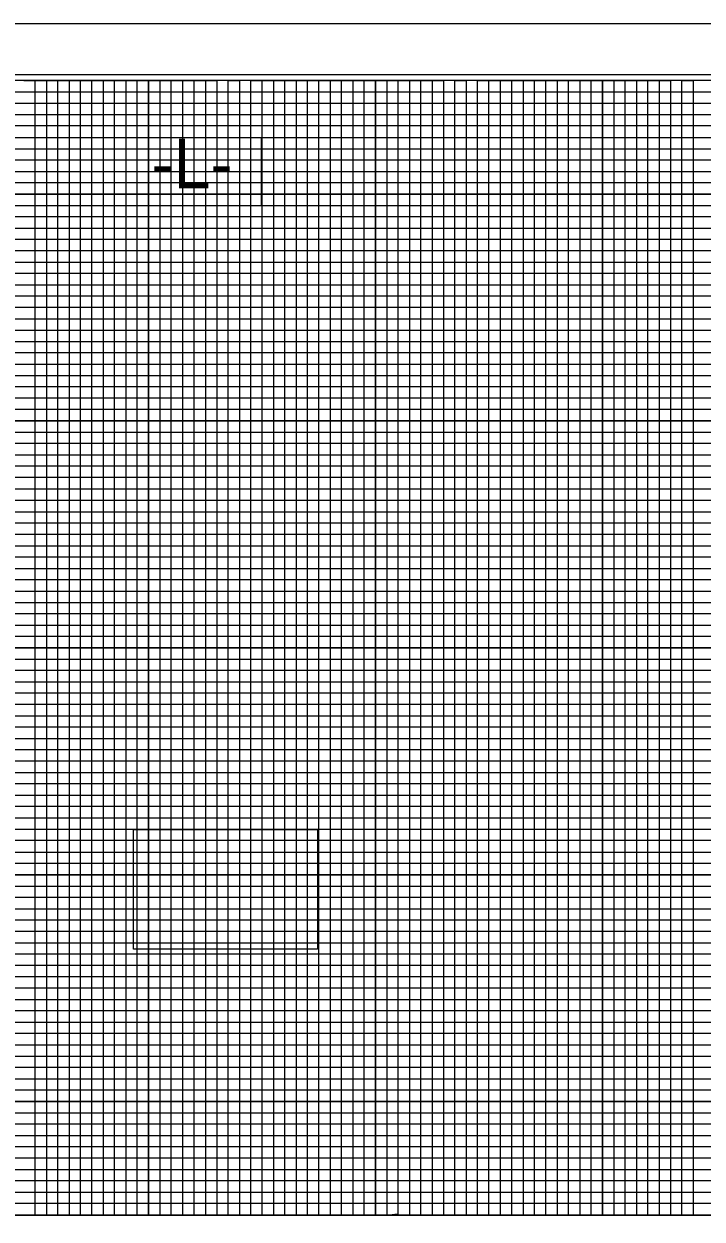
# Model space of a CAD drawing. Extents: x 1623313 to 1628771, y 891211 to 901910.
# Drawn here: x 1624175 to 1624474, y 901333 to 901859 of the extents above; entities that cross this region are included whole.
import ezdxf

# ---------------------------------------------------------------- set-up
doc = ezdxf.new("R2010")
doc.units = 0
for name, color, linetype in [('Prop DSN Text', 7, 'Continuous'), ('Prop PHM Black Shape', 7, 'Continuous'), ('Scratch_Level_0', 7, 'Continuous'), ('Sheet Cutting Line CELL', 7, 'Continuous'), ('Sheet DOT Grid CELL', 7, 'Continuous'), ('Sheet Layout Profile Border Port 1', 7, 'Continuous'), ('Sheet Plot Border Inside CELL', 7, 'Continuous'), ('Sheet Plot Border Outside CELL', 7, 'Continuous'), ('Sheet Profile CELL', 7, 'Continuous'), ('Sheet Profile Grid Major CELL', 7, 'Continuous'), ('Sheet Profile Grid Middle CELL', 7, 'Continuous'), ('Sheet Profile Grid Minor CELL', 7, 'Continuous')]:
    doc.layers.add(name, color=color, linetype=linetype)

msp = doc.modelspace()

# ---------------------------------------------------------------- linework, layer by layer
at = {"layer": 'Prop DSN Text'}
msp.add_lwpolyline([(1624229.95, 901809.45), (1624279.54, 901809.45), (1624279.54, 901779.22), (1624229.95, 901779.22)], close=True, dxfattribs=at)
at = {"layer": 'Prop PHM Black Shape'}
for points in [[(1624229.95, 901809.45), (1624279.54, 901809.45), (1624279.54, 901779.22), (1624229.95, 901779.22)], [(1624223.32, 901504.36), (1624304.32, 901504.36), (1624304.32, 901451.64), (1624223.32, 901451.64)]]:
    msp.add_lwpolyline(points, close=True, dxfattribs=at)
at = {"layer": 'Scratch_Level_0'}
msp.add_lwpolyline([(1623529.95, 901824.45), (1624929.95, 901824.45), (1624929.95, 901334.45), (1623529.95, 901334.45)], close=True, dxfattribs=at)
at = {"layer": 'Sheet Cutting Line CELL'}
msp.add_line((1624996.95, 901859.45), (1623312.95, 901859.45), dxfattribs=at)
at = {"layer": 'Sheet DOT Grid CELL'}
for p, q in [((1624179.95, 901334.45), (1624179.95, 901834.45)), ((1624229.95, 901334.45), (1624229.95, 901834.45)), ((1624279.95, 901334.45), (1624279.95, 901834.45)), ((1624329.95, 901334.45), (1624329.95, 901834.45)), ((1624379.95, 901334.45), (1624379.95, 901834.45)), ((1624429.95, 901334.45), (1624429.95, 901834.45)), ((1624779.9, 901784.45), (1623479.95, 901784.45)), ((1624779.9, 901734.45), (1623479.95, 901734.45)), ((1624779.95, 901684.45), (1623479.95, 901684.45)), ((1624979.95, 901634.45), (1623479.95, 901634.45)), ((1624979.95, 901584.45), (1623479.95, 901584.45)), ((1624979.95, 901534.45), (1623479.95, 901534.45)), ((1624979.95, 901484.45), (1623479.95, 901484.45)), ((1624979.95, 901434.45), (1623479.95, 901434.45)), ((1624979.95, 901384.45), (1623479.95, 901384.45))]:
    msp.add_line(p, q, dxfattribs=at)
at = {"layer": 'Sheet Layout Profile Border Port 1'}
msp.add_lwpolyline([(1623529.95, 901673.4), (1623529.95, 901334.45), (1624929.95, 901334.45), (1624929.95, 901673.4)], dxfattribs=at)
at = {"layer": 'Sheet Plot Border Inside CELL'}
msp.add_lwpolyline([(1623325.95, 900781.9), (1624992.45, 900781.9), (1624992.45, 901837), (1623325.95, 901837)], close=True, dxfattribs=at)
at = {"layer": 'Sheet Plot Border Outside CELL'}
msp.add_lwpolyline([(1623312.95, 900759.45), (1624996.95, 900759.45), (1624996.95, 901859.45), (1623312.95, 901859.45)], close=True, dxfattribs=at)
at = {"layer": 'Sheet Profile CELL'}
msp.add_line((1623479.95, 901334.45), (1624979.95, 901334.45), dxfattribs=at)
msp.add_lwpolyline([(1624979.95, 901834.45), (1623479.95, 901834.45), (1623479.95, 900784.45), (1624979.95, 900784.45)], close=True, dxfattribs=at)
at = {"layer": 'Sheet Profile Grid Major CELL'}
for points in [[(1624129.95, 901334.45), (1624179.95, 901334.45), (1624179.95, 901834.45), (1624229.95, 901834.45), (1624229.95, 901334.45), (1624279.95, 901334.45), (1624279.95, 901834.45), (1624329.95, 901834.45), (1624329.95, 901334.45), (1624379.95, 901334.45), (1624379.95, 901834.45), (1624429.95, 901834.45), (1624429.95, 901334.45), (1624479.95, 901334.45)], [(1623479.95, 901784.45), (1624779.95, 901784.45)], [(1624779.95, 901734.45), (1623479.95, 901734.45), (1623479.95, 901684.45), (1624779.95, 901684.45)], [(1624979.95, 901634.45), (1623479.95, 901634.45), (1623479.95, 901584.45), (1624979.95, 901584.45)], [(1624979.95, 901534.45), (1623479.95, 901534.45), (1623479.95, 901484.45), (1624979.95, 901484.45)], [(1624979.95, 901434.45), (1623479.95, 901434.45), (1623479.95, 901434.45), (1623479.95, 901384.45), (1624979.95, 901384.45)]]:
    msp.add_lwpolyline(points, dxfattribs=at)
at = {"layer": 'Sheet Profile Grid Middle CELL'}
msp.add_line((1623479.95, 901809.45), (1624779.9, 901809.45), dxfattribs=at)
for points in [[(1624154.95, 901334.45), (1624204.95, 901334.45), (1624204.95, 901834.45), (1624254.95, 901834.45), (1624254.95, 901334.45), (1624304.95, 901334.45), (1624304.95, 901834.45), (1624354.95, 901834.45), (1624354.95, 901334.45), (1624404.95, 901334.45), (1624404.95, 901834.45), (1624454.95, 901834.45), (1624454.95, 901334.45), (1624504.95, 901334.45)], [(1624779.95, 901759.45), (1623479.95, 901759.45), (1623479.95, 901709.45), (1624779.95, 901709.45)], [(1624979.95, 901659.45), (1623479.95, 901659.45), (1623479.95, 901609.45), (1624804.95, 901609.45)], [(1624979.95, 901559.45), (1623479.95, 901559.45), (1623479.95, 901509.45), (1624979.95, 901509.45)], [(1624979.95, 901459.45), (1623479.95, 901459.45), (1623479.95, 901409.45), (1624979.95, 901409.45)], [(1624979.95, 901359.45), (1623479.95, 901359.45)]]:
    msp.add_lwpolyline(points, dxfattribs=at)
at = {"layer": 'Sheet Profile Grid Minor CELL'}
for p, q in [((1623529.95, 901829.45), (1624779.95, 901829.45)), ((1624779.95, 901824.45), (1623529.95, 901824.1)), ((1623529.95, 901819.45), (1624779.95, 901819.45)), ((1624779.9, 901699.45), (1623529.95, 901699.45)), ((1624779.95, 901694.45), (1623529.95, 901694.45)), ((1624779.95, 901689.45), (1623529.95, 901689.45)), ((1623529.95, 901679.45), (1624779.95, 901679.45)), ((1624779.95, 901674.45), (1623529.95, 901674.45)), ((1623529.95, 901669.45), (1624929.95, 901669.45)), ((1624929.95, 901649.45), (1623529.95, 901649.45)), ((1623529.95, 901644.45), (1624929.95, 901644.45)), ((1624929.95, 901624.45), (1623529.95, 901624.45)), ((1623529.95, 901619.45), (1624929.95, 901619.45)), ((1624929.95, 901599.45), (1623529.95, 901599.45)), ((1623529.95, 901594.45), (1624929.95, 901594.45)), ((1624929.95, 901589.45), (1623529.95, 901589.45)), ((1623529.95, 901579.45), (1624929.95, 901579.45)), ((1624929.95, 901574.45), (1623529.95, 901574.45)), ((1623529.95, 901569.45), (1624929.95, 901569.45)), ((1624929.95, 901564.45), (1623529.95, 901564.45)), ((1623529.95, 901554.45), (1624929.95, 901554.45)), ((1624929.95, 901549.45), (1623529.95, 901549.45)), ((1623529.95, 901544.45), (1624929.95, 901544.45)), ((1624929.95, 901539.45), (1623529.95, 901539.45)), ((1623529.95, 901529.45), (1624929.95, 901529.45)), ((1624929.95, 901524.45), (1623529.95, 901524.45)), ((1623529.95, 901519.45), (1624929.95, 901519.45)), ((1624929.95, 901514.45), (1623529.95, 901514.45)), ((1623529.95, 901504.45), (1624929.95, 901504.45)), ((1624929.95, 901499.45), (1623529.95, 901499.45)), ((1623529.95, 901494.45), (1624929.95, 901494.45)), ((1624929.95, 901489.45), (1623529.95, 901489.45)), ((1623529.95, 901479.45), (1624929.95, 901479.45)), ((1624929.95, 901474.45), (1623529.95, 901474.45)), ((1623529.95, 901469.45), (1624929.95, 901469.45)), ((1624929.95, 901464.45), (1623529.95, 901464.45)), ((1623529.95, 901454.45), (1624929.95, 901454.45)), ((1624929.95, 901449.45), (1623529.95, 901449.45)), ((1624929.95, 901444.45), (1623529.95, 901444.45)), ((1624929.95, 901439.45), (1623529.95, 901439.45)), ((1623529.95, 901429.45), (1624929.95, 901429.45)), ((1624929.95, 901424.45), (1623529.95, 901424.45)), ((1623529.95, 901419.45), (1624929.95, 901419.45)), ((1624929.95, 901414.45), (1623529.95, 901414.45)), ((1623529.95, 901404.45), (1624929.95, 901404.45)), ((1624929.95, 901399.45), (1623529.95, 901399.45)), ((1623529.95, 901394.45), (1624929.95, 901394.45)), ((1624929.95, 901389.45), (1623529.95, 901389.45)), ((1623529.95, 901379.45), (1624929.95, 901379.45)), ((1624929.95, 901374.45), (1623529.95, 901374.45)), ((1623529.95, 901369.45), (1624929.95, 901369.45)), ((1624929.95, 901364.45), (1623529.95, 901364.45)), ((1623529.95, 901354.45), (1624929.95, 901354.45)), ((1624929.95, 901349.45), (1623529.95, 901349.45)), ((1623529.95, 901344.45), (1624929.95, 901344.45))]:
    msp.add_line(p, q, dxfattribs=at)
for points in [[(1624174.95, 901834.45), (1624184.95, 901834.45), (1624184.95, 901334.45), (1624184.95, 901334.45), (1624189.95, 901334.45), (1624189.95, 901834.45), (1624194.95, 901834.45), (1624194.95, 901334.45), (1624199.95, 901334.45), (1624199.95, 901834.45), (1624209.95, 901834.45), (1624209.95, 901334.45), (1624214.95, 901334.45), (1624214.95, 901834.45), (1624219.95, 901834.45), (1624219.95, 901334.45), (1624224.95, 901334.45), (1624224.95, 901834.45), (1624234.95, 901834.45), (1624234.95, 901334.45), (1624239.95, 901334.45), (1624239.95, 901834.45), (1624244.95, 901834.45), (1624244.95, 901334.45), (1624249.95, 901334.45), (1624249.95, 901834.45), (1624259.95, 901834.45), (1624259.95, 901334.45), (1624264.95, 901334.45), (1624264.95, 901834.45), (1624269.95, 901834.45), (1624269.95, 901334.45), (1624274.95, 901334.45), (1624274.95, 901834.45), (1624284.95, 901834.45), (1624284.95, 901334.45), (1624289.95, 901334.45), (1624289.95, 901834.45), (1624294.95, 901834.45), (1624294.95, 901334.45), (1624299.95, 901334.45), (1624299.95, 901834.45), (1624309.95, 901834.45), (1624309.95, 901334.45), (1624314.95, 901334.45), (1624314.95, 901834.45), (1624319.95, 901834.45), (1624319.95, 901334.45), (1624324.95, 901334.45), (1624324.95, 901834.45), (1624334.95, 901834.45), (1624334.95, 901334.45), (1624339.65, 901335), (1624339.95, 901334.45), (1624339.95, 901834.45), (1624344.95, 901834.45), (1624344.95, 901334.45), (1624349.95, 901334.45), (1624349.95, 901834.45), (1624359.95, 901834.45), (1624359.95, 901334.45), (1624364.95, 901334.45)], [(1624364.95, 901334.45), (1624364.95, 901834.45), (1624369.95, 901834.45), (1624369.95, 901334.45), (1624374.95, 901334.45), (1624374.95, 901834.45), (1624384.95, 901834.45), (1624384.95, 901334.45), (1624389.95, 901334.45), (1624389.95, 901834.45), (1624394.95, 901834.45), (1624394.95, 901334.45), (1624399.95, 901334.45), (1624399.95, 901834.45), (1624409.95, 901834.45), (1624409.95, 901334.45), (1624414.95, 901334.45), (1624414.95, 901834.45), (1624419.95, 901834.45), (1624419.95, 901334.45), (1624424.95, 901334.45), (1624424.95, 901834.45), (1624434.95, 901834.45), (1624434.95, 901334.45), (1624439.95, 901334.45), (1624439.95, 901834.45), (1624444.95, 901834.45), (1624444.95, 901334.45), (1624449.95, 901334.45), (1624449.95, 901834.45), (1624459.95, 901834.45), (1624459.95, 901334.45), (1624464.95, 901334.45), (1624464.95, 901834.45), (1624469.95, 901834.45), (1624469.95, 901334.45), (1624474.95, 901334.45)], [(1624779.95, 901814.45), (1623529.95, 901814.45), (1623529.95, 901804.45), (1624779.95, 901804.45)], [(1624779.9, 901799.45), (1623529.95, 901799.45), (1623529.95, 901794.45), (1624779.95, 901794.45)], [(1624779.95, 901789.45), (1623529.95, 901789.45), (1623529.95, 901779.45), (1624779.95, 901779.45)], [(1624779.95, 901774.45), (1623529.95, 901774.45), (1623529.95, 901769.45), (1624779.95, 901769.45)], [(1624779.95, 901764.45), (1623529.95, 901764.45), (1623529.95, 901754.45), (1624779.95, 901754.45)], [(1624779.95, 901749.45), (1623529.95, 901749.45), (1623529.95, 901744.45), (1624779.95, 901744.45)], [(1624779.95, 901739.45), (1623529.95, 901739.45), (1623529.95, 901729.45), (1624779.95, 901729.45)], [(1624779.95, 901724.35), (1623530.05, 901724.35), (1623530.05, 901719.45), (1624779.95, 901719.45)], [(1624779.95, 901714.45), (1623529.95, 901714.45), (1623529.95, 901704.45), (1624779.95, 901704.45)], [(1624929.95, 901664.45), (1623529.95, 901664.45), (1623529.95, 901654.45), (1624929.95, 901654.45)], [(1624929.95, 901639.45), (1623529.95, 901639.45), (1623529.95, 901629.45), (1624929.95, 901629.45)], [(1624929.95, 901614.45), (1623529.95, 901614.45), (1623529.95, 901604.45), (1624929.95, 901604.45)], [(1624929.95, 901339.45), (1623529.95, 901339.45)]]:
    msp.add_lwpolyline(points, dxfattribs=at)

# ---------------------------------------------------------------- texts
at = {"layer": 'Prop DSN Text'}
msp.add_text('-L-', height=21.875, dxfattribs=at).set_placement((1624231.18, 901786.94))

doc.saveas('drawing.dxf')
